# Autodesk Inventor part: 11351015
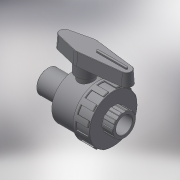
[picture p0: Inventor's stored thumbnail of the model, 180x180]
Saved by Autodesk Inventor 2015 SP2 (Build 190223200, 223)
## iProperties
Created: 2017-11
Part Number: 11351015
Material: Generic
Description: PLASSON 1/NUT VALVE FEMALE THREADED 1 1/2" PVC
Document SubType Name: Modeling
Designer: KIM
Density: 1 g/cm^3
Appearance: Default
Author: KIM
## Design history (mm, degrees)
derived "113510.ipt"
feature "Solid1::113510.ipt"
tag "TaggingFeature1"
body "Solid1"
other parameters: "d0" = 138, "d2" = 96, "d4" = 35.876, "d8" = 86.4, "d13" = 1.34535, "d25" = 0.8969, "d26" = 1.34535, "d29" = 23.25, "d30" = 0, "d35" = 1.34535, "d39" = 48, "d45" = 360 deg, "d47" = 0.8969, "d50" = 52.8, "d51" = 28.8, "d53" = 0, "d55" = 8.969, "d56" = 4.4845, "d57" = 21.7, "d58" = 0, "d59" = 1.34535, "d63" = 38.4, "d64" = 86, "d68" = 19.2, "d69" = 33, "d70" = 21.5, "d71" = 3 deg, "d73" = 1.92, "d74" = 44, "d75" = 2.58, "d76" = 0, "d77" = 0.8969, "d78" = 44.845, "d79" = 31, "d80" = 96, "d81" = 31, "d82" = 92.16, "d83" = 21.7, "d84" = 62.783, "d85" = 44.845, "d86" = 62.783, "d87" = 120 deg, "d88" = 31, "d90" = 360 deg, "d92" = 14.4, "d95" = 7.2, "G_" = 44.845, "l_" = 31, "H_" = 138, "K_" = 96, "F_" = 86, "d67" = 38.4, "d72" = 9.6
